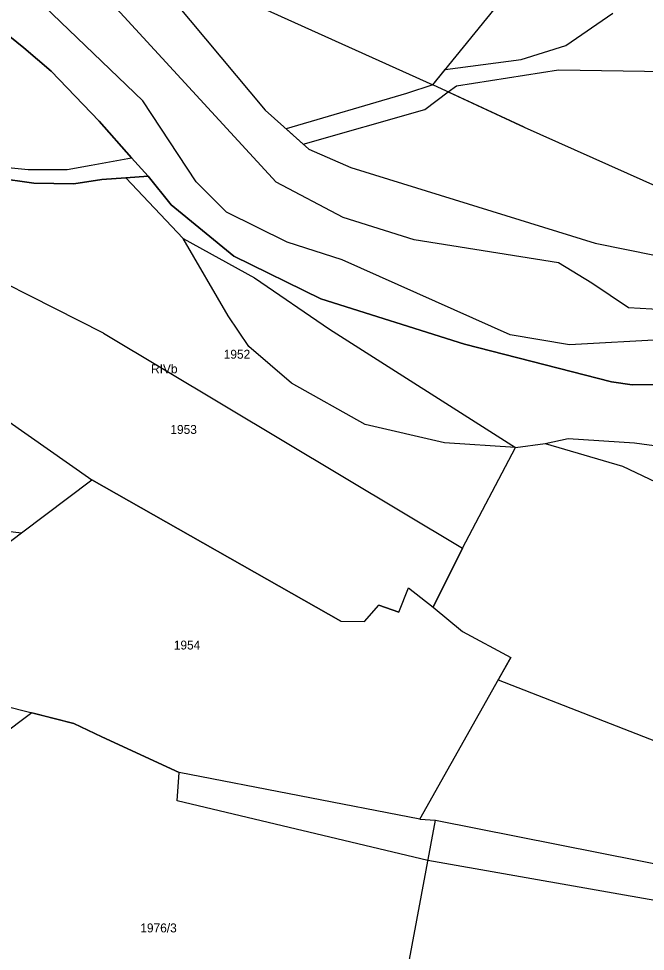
# Model space of a CAD drawing. Extents: x 7498273 to 7499989, y 5499795 to 5500810.
# Drawn here: x 7499281.1 to 7499386.6, y 5500066 to 5500223.1 of the extents above; entities that cross this region are included whole.
import ezdxf

# ---------------------------------------------------------------- set-up
doc = ezdxf.new("R2010")
doc.units = 0
for name, color, linetype in [('209-oznaczenie konturu klasyfikacyjnego', 7, 'Continuous'), ('211-numer działki ewidencyjnej', 7, 'Continuous'), ('217-kontur klasyfikacyjny', 7, 'Continuous'), ('218-kontur użytku gruntowego', 7, 'Continuous'), ('219-działka ewidencyjna', 7, 'Continuous')]:
    doc.layers.add(name, color=color, linetype=linetype)

msp = doc.modelspace()

# ---------------------------------------------------------------- linework, layer by layer
at = {"layer": '217-kontur klasyfikacyjny'}
for points in [[(7499303.11, 5500233.48), (7499350.77, 5500211.94)], [(7499373.19, 5500218.55), (7499381.1, 5500224.01)], [(7499281.96, 5500218.16), (7499278.44, 5500221.02)], [(7499365.67, 5500216.2), (7499373.19, 5500218.55)], [(7499286.54, 5500214.24), (7499281.96, 5500218.16)], [(7499352.87, 5500214.53), (7499365.67, 5500216.2)], [(7499294.63, 5500205.82), (7499286.54, 5500214.24)], [(7499350.77, 5500211.94), (7499352.87, 5500214.53)], [(7499354.75, 5500211.76), (7499371.92, 5500214.47)], [(7499371.92, 5500214.47), (7499444.36, 5500213.36)], [(7499350.77, 5500211.94), (7499346.35, 5500210.47)], [(7499349.47, 5500207.77), (7499353.39, 5500210.73)], [(7499353.39, 5500210.73), (7499354.75, 5500211.76)], [(7499353.39, 5500210.73), (7499366.18, 5500204.81)], [(7499346.35, 5500210.47), (7499326.1, 5500204.51)], [(7499328.96, 5500201.96), (7499349.47, 5500207.77)], [(7499300.1, 5500199.63), (7499294.63, 5500205.82)], [(7499326.1, 5500204.51), (7499328.96, 5500201.96)], [(7499366.18, 5500204.81), (7499391.89, 5500193.3)], [(7499293.31, 5500198.43), (7499300.1, 5500199.63)], [(7499302.86, 5500196.56), (7499300.1, 5500199.63)], [(7499274.15, 5500198.51), (7499282.68, 5500197.66)], [(7499289.25, 5500197.68), (7499293.31, 5500198.43)], [(7499282.68, 5500197.66), (7499289.25, 5500197.68)], [(7499302.86, 5500196.56), (7499299.1, 5500196.27)], [(7499306.78, 5500191.71), (7499302.86, 5500196.56)], [(7499283.63, 5500195.35), (7499277.25, 5500196.3)], [(7499290.37, 5500195.25), (7499283.63, 5500195.35)], [(7499295.1, 5500195.97), (7499290.37, 5500195.25)], [(7499299.1, 5500196.27), (7499295.1, 5500195.97)], [(7499308.77, 5500186.05), (7499299.1, 5500196.27)], [(7499317.29, 5500183.07), (7499306.78, 5500191.71)], [(7499316.36, 5500173.04), (7499308.77, 5500186.05)], [(7499331.97, 5500175.88), (7499317.29, 5500183.07)], [(7499356.11, 5500168.26), (7499331.97, 5500175.88)], [(7499319.8, 5500167.87), (7499316.36, 5500173.04)], [(7499257.43, 5500170.6), (7499293.39, 5500145.42)], [(7499380.84, 5500161.93), (7499356.11, 5500168.26)], [(7499326.98, 5500161.73), (7499319.8, 5500167.87)], [(7499384.35, 5500161.44), (7499380.84, 5500161.93)], [(7499339.39, 5500154.76), (7499326.98, 5500161.73)], [(7499400.53, 5500161.51), (7499384.35, 5500161.44)], [(7499352.75, 5500151.67), (7499339.39, 5500154.76)], [(7499364.69, 5500150.88), (7499352.75, 5500151.67)], [(7499355.81, 5500133.92), (7499364.69, 5500150.88)], [(7499364.69, 5500150.88), (7499369.69, 5500151.54)], [(7499369.69, 5500151.54), (7499373.55, 5500152.39)], [(7499373.55, 5500152.39), (7499384.75, 5500151.66)], [(7499384.75, 5500151.66), (7499398.39, 5500149.78)], [(7499293.39, 5500145.42), (7499335.31, 5500121.64)], [(7499350.83, 5500123.98), (7499355.81, 5500133.92)], [(7499345.07, 5500123.15), (7499346.68, 5500127.26)], [(7499346.68, 5500127.26), (7499350.83, 5500123.98)], [(7499339.27, 5500121.6), (7499341.69, 5500124.3)], [(7499341.69, 5500124.3), (7499345.07, 5500123.15)], [(7499350.83, 5500123.98), (7499355.76, 5500119.91)], [(7499335.31, 5500121.64), (7499339.27, 5500121.6)], [(7499355.76, 5500119.91), (7499363.91, 5500115.52)], [(7499363.91, 5500115.52), (7499361.78, 5500111.74)], [(7499361.78, 5500111.74), (7499393.86, 5500099.23)], [(7499283.33, 5500106.19), (7499261.72, 5500089.98)], [(7499290.4, 5500104.39), (7499283.33, 5500106.19)], [(7499295.06, 5500102.14), (7499290.4, 5500104.39)], [(7499308.11, 5500096.14), (7499295.06, 5500102.14)], [(7499307.76, 5500091.4), (7499308.11, 5500096.14)], [(7499349.96, 5500081.32), (7499307.76, 5500091.4)], [(7499391.03, 5500074.12), (7499349.96, 5500081.32)]]:
    msp.add_lwpolyline(points, dxfattribs=at)
at = {"layer": '218-kontur użytku gruntowego'}
for points in [[(7499303.11, 5500233.48), (7499350.77, 5500211.94)], [(7499324.4, 5500195.55), (7499294.34, 5500228.32)], [(7499301.97, 5500209.24), (7499285.41, 5500225.16)], [(7499373.19, 5500218.55), (7499381.1, 5500224.01)], [(7499281.96, 5500218.16), (7499278.44, 5500221.02)], [(7499365.67, 5500216.2), (7499373.19, 5500218.55)], [(7499286.54, 5500214.24), (7499281.96, 5500218.16)], [(7499352.87, 5500214.53), (7499365.67, 5500216.2)], [(7499294.63, 5500205.82), (7499286.54, 5500214.24)], [(7499350.77, 5500211.94), (7499352.87, 5500214.53)], [(7499354.75, 5500211.76), (7499371.92, 5500214.47)], [(7499371.92, 5500214.47), (7499444.36, 5500213.36)], [(7499350.77, 5500211.94), (7499346.35, 5500210.47)], [(7499349.47, 5500207.77), (7499353.39, 5500210.73)], [(7499353.39, 5500210.73), (7499354.75, 5500211.76)], [(7499353.39, 5500210.73), (7499366.18, 5500204.81)], [(7499310.94, 5500195.58), (7499301.97, 5500209.24)], [(7499346.35, 5500210.47), (7499326.1, 5500204.51)], [(7499328.96, 5500201.96), (7499349.47, 5500207.77)], [(7499300.1, 5500199.63), (7499294.63, 5500205.82)], [(7499326.1, 5500204.51), (7499328.96, 5500201.96)], [(7499366.18, 5500204.81), (7499391.89, 5500193.3)], [(7499293.31, 5500198.43), (7499300.1, 5500199.63)], [(7499300.1, 5500199.63), (7499302.86, 5500196.56)], [(7499274.15, 5500198.51), (7499282.68, 5500197.66)], [(7499289.25, 5500197.68), (7499293.31, 5500198.43)], [(7499282.68, 5500197.66), (7499289.25, 5500197.68)], [(7499302.86, 5500196.56), (7499299.1, 5500196.27)], [(7499302.86, 5500196.56), (7499306.78, 5500191.71)], [(7499283.63, 5500195.35), (7499277.25, 5500196.3)], [(7499290.37, 5500195.25), (7499283.63, 5500195.35)], [(7499295.1, 5500195.97), (7499290.37, 5500195.25)], [(7499299.1, 5500196.27), (7499295.1, 5500195.97)], [(7499308.77, 5500186.05), (7499299.1, 5500196.27)], [(7499316.06, 5500190.5), (7499310.94, 5500195.58)], [(7499335.71, 5500189.62), (7499324.4, 5500195.55)], [(7499306.78, 5500191.71), (7499317.29, 5500183.07)], [(7499326.27, 5500185.47), (7499316.06, 5500190.5)], [(7499347.64, 5500185.82), (7499335.71, 5500189.62)], [(7499316.36, 5500173.04), (7499308.77, 5500186.05)], [(7499335.52, 5500182.48), (7499326.27, 5500185.47)], [(7499371.92, 5500181.96), (7499347.64, 5500185.82)], [(7499317.29, 5500183.07), (7499331.97, 5500175.88)], [(7499363.81, 5500169.86), (7499335.52, 5500182.48)], [(7499377.56, 5500178.54), (7499371.92, 5500181.96)], [(7499383.7, 5500174.4), (7499377.56, 5500178.54)], [(7499331.97, 5500175.88), (7499356.11, 5500168.26)], [(7499319.8, 5500167.87), (7499316.36, 5500173.04)], [(7499395.49, 5500173.71), (7499383.7, 5500174.4)], [(7499257.43, 5500170.6), (7499293.39, 5500145.42)], [(7499373.81, 5500168.13), (7499363.81, 5500169.86)], [(7499406.2, 5500169.98), (7499373.81, 5500168.13)], [(7499356.11, 5500168.26), (7499380.84, 5500161.93)], [(7499326.98, 5500161.73), (7499319.8, 5500167.87)], [(7499380.84, 5500161.93), (7499384.35, 5500161.44)], [(7499339.39, 5500154.76), (7499326.98, 5500161.73)], [(7499384.35, 5500161.44), (7499400.53, 5500161.51)], [(7499352.75, 5500151.67), (7499339.39, 5500154.76)], [(7499364.69, 5500150.88), (7499352.75, 5500151.67)], [(7499355.81, 5500133.92), (7499364.69, 5500150.88)], [(7499364.69, 5500150.88), (7499369.69, 5500151.54)], [(7499369.69, 5500151.54), (7499373.55, 5500152.39)], [(7499373.55, 5500152.39), (7499384.75, 5500151.66)], [(7499384.75, 5500151.66), (7499398.39, 5500149.78)], [(7499293.39, 5500145.42), (7499335.31, 5500121.64)], [(7499350.83, 5500123.98), (7499355.81, 5500133.92)], [(7499345.07, 5500123.15), (7499346.68, 5500127.26)], [(7499346.68, 5500127.26), (7499350.83, 5500123.98)], [(7499339.27, 5500121.6), (7499341.69, 5500124.3)], [(7499341.69, 5500124.3), (7499345.07, 5500123.15)], [(7499350.83, 5500123.98), (7499355.76, 5500119.91)], [(7499335.31, 5500121.64), (7499339.27, 5500121.6)], [(7499355.76, 5500119.91), (7499363.91, 5500115.52)], [(7499363.91, 5500115.52), (7499361.78, 5500111.74)], [(7499361.78, 5500111.74), (7499393.86, 5500099.23)], [(7499283.33, 5500106.19), (7499261.72, 5500089.98)], [(7499290.4, 5500104.39), (7499283.33, 5500106.19)], [(7499295.06, 5500102.14), (7499290.4, 5500104.39)], [(7499308.11, 5500096.14), (7499295.06, 5500102.14)], [(7499307.76, 5500091.4), (7499308.11, 5500096.14)], [(7499349.96, 5500081.32), (7499307.76, 5500091.4)], [(7499391.03, 5500074.12), (7499349.96, 5500081.32)]]:
    msp.add_lwpolyline(points, dxfattribs=at)
at = {"layer": '219-działka ewidencyjna'}
for points in [[(7499350.77, 5500211.94), (7499388.36, 5500258.19)], [(7499303.11, 5500233.48), (7499350.77, 5500211.94)], [(7499305.06, 5500228.64), (7499322.55, 5500207.66)], [(7499278.44, 5500221.02), (7499281.96, 5500218.16)], [(7499281.96, 5500218.16), (7499286.54, 5500214.24)], [(7499286.54, 5500214.24), (7499294.63, 5500205.82)], [(7499366.18, 5500204.81), (7499350.77, 5500211.94)], [(7499322.55, 5500207.66), (7499329.94, 5500201.09)], [(7499294.63, 5500205.82), (7499300.1, 5500199.63)], [(7499366.18, 5500204.81), (7499391.89, 5500193.3)], [(7499293.31, 5500198.43), (7499300.1, 5500199.63)], [(7499302.86, 5500196.56), (7499300.1, 5500199.63)], [(7499329.94, 5500201.09), (7499336.98, 5500198)], [(7499274.15, 5500198.51), (7499282.68, 5500197.66)], [(7499289.25, 5500197.68), (7499293.31, 5500198.43)], [(7499336.98, 5500198), (7499378.12, 5500185.25)], [(7499282.68, 5500197.66), (7499289.25, 5500197.68)], [(7499299.1, 5500196.27), (7499302.86, 5500196.56)], [(7499302.86, 5500196.56), (7499306.78, 5500191.71)], [(7499277.25, 5500196.3), (7499283.63, 5500195.35)], [(7499283.63, 5500195.35), (7499290.37, 5500195.25)], [(7499290.37, 5500195.25), (7499295.1, 5500195.97)], [(7499295.1, 5500195.97), (7499299.1, 5500196.27)], [(7499299.1, 5500196.27), (7499308.77, 5500186.05)], [(7499306.78, 5500191.71), (7499317.29, 5500183.07)], [(7499308.77, 5500186.05), (7499320.78, 5500179.43)], [(7499295.36, 5500170.12), (7499266.51, 5500184.72)], [(7499378.12, 5500185.25), (7499388.36, 5500183.19)], [(7499317.29, 5500183.07), (7499331.97, 5500175.88)], [(7499320.78, 5500179.43), (7499333.39, 5500170.78)], [(7499331.97, 5500175.88), (7499356.11, 5500168.26)], [(7499257.43, 5500170.6), (7499293.39, 5500145.42)], [(7499295.36, 5500170.12), (7499355.81, 5500133.92)], [(7499333.39, 5500170.78), (7499364.69, 5500150.88)], [(7499356.11, 5500168.26), (7499380.84, 5500161.93)], [(7499380.84, 5500161.93), (7499384.35, 5500161.44)], [(7499384.35, 5500161.44), (7499400.53, 5500161.51)], [(7499355.81, 5500133.92), (7499364.69, 5500150.88)], [(7499364.69, 5500150.88), (7499369.69, 5500151.54)], [(7499369.69, 5500151.54), (7499373.55, 5500152.39)], [(7499369.69, 5500151.54), (7499382.71, 5500147.73)], [(7499373.55, 5500152.39), (7499384.75, 5500151.66)], [(7499384.75, 5500151.66), (7499398.39, 5500149.78)], [(7499382.71, 5500147.73), (7499391.71, 5500143.49)], [(7499281.57, 5500136.52), (7499293.39, 5500145.42)], [(7499335.31, 5500121.64), (7499293.39, 5500145.42)], [(7499226.03, 5500143.16), (7499281.57, 5500136.52)], [(7499250.49, 5500112.93), (7499281.57, 5500136.52)], [(7499355.81, 5500133.92), (7499350.83, 5500123.98)], [(7499345.07, 5500123.15), (7499346.68, 5500127.26)], [(7499346.68, 5500127.26), (7499350.83, 5500123.98)], [(7499339.27, 5500121.6), (7499341.69, 5500124.3)], [(7499345.07, 5500123.15), (7499341.69, 5500124.3)], [(7499350.83, 5500123.98), (7499355.76, 5500119.91)], [(7499335.31, 5500121.64), (7499339.27, 5500121.6)], [(7499355.76, 5500119.91), (7499363.91, 5500115.52)], [(7499348.59, 5500088.3), (7499363.91, 5500115.52)], [(7499265.93, 5500110.61), (7499290.4, 5500104.39)], [(7499290.4, 5500104.39), (7499295.06, 5500102.14)], [(7499295.06, 5500102.14), (7499308.11, 5500096.14)], [(7499348.59, 5500088.3), (7499308.11, 5500096.14)], [(7499341.79, 5500037.59), (7499351.23, 5500088.12)], [(7499348.59, 5500088.3), (7499351.23, 5500088.12)], [(7499351.23, 5500088.12), (7499392.54, 5500079.96)]]:
    msp.add_lwpolyline(points, dxfattribs=at)

# ---------------------------------------------------------------- texts
at = {"layer": '209-oznaczenie konturu klasyfikacyjnego'}
msp.add_text('RIVb', height=1.5, dxfattribs=at).set_placement((7499303.37, 5500163.37))
at = {"layer": '211-numer działki ewidencyjnej'}
for s, p in [('1952', (7499315.6, 5500165.82)), ('1953', (7499306.62, 5500153.16)), ('1954', (7499307.2, 5500116.86)), ('1976/3', (7499301.56, 5500069.23))]:
    msp.add_text(s, height=1.5, dxfattribs=at).set_placement(p)

doc.saveas('drawing.dxf')
